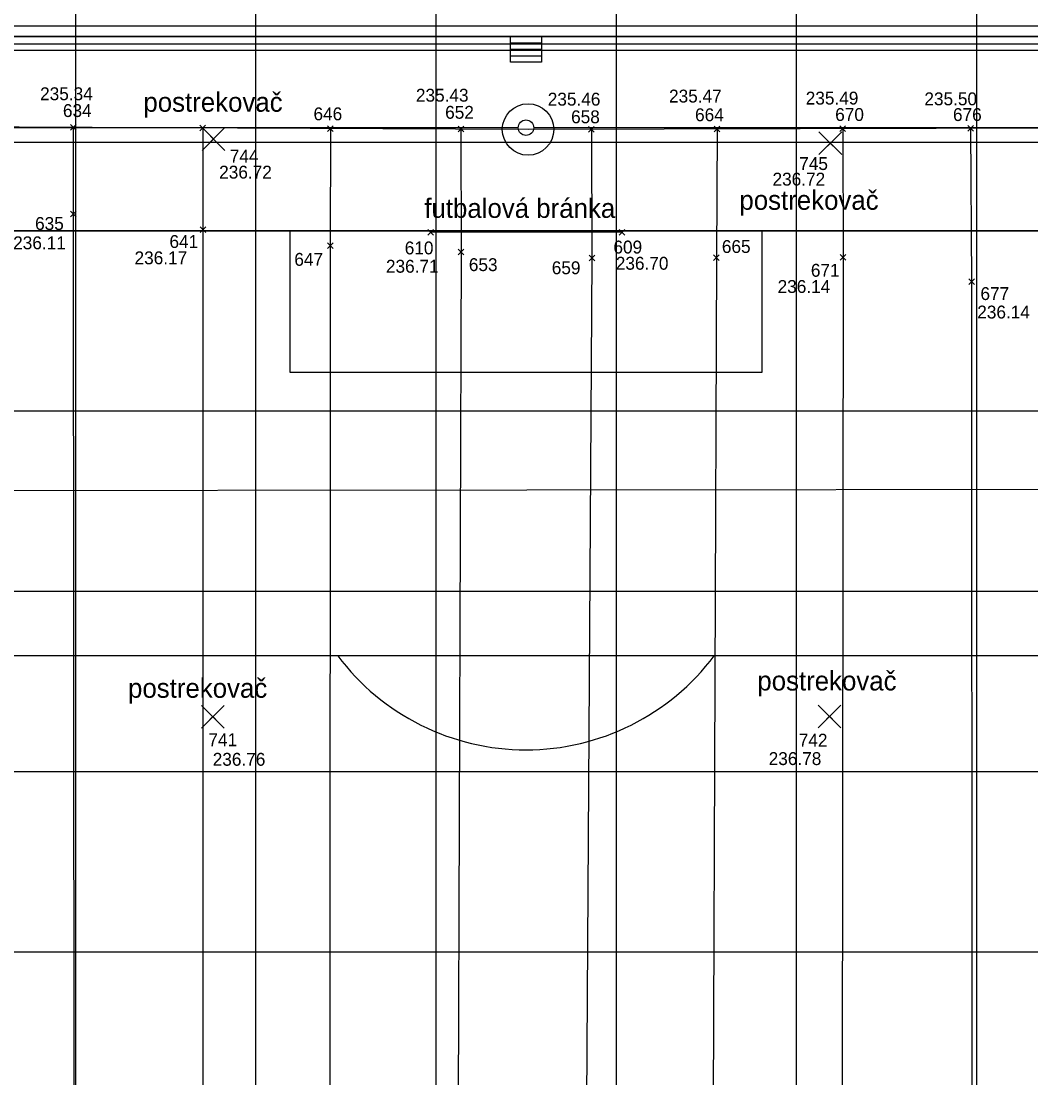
# Model space of a CAD drawing. Extents: x -264205 to -263659, y -1242401 to -1242060.
# Drawn here: x -263871.58 to -263832.36, y -1242144.77 to -1242103.74 of the extents above; entities that cross this region are included whole.
import ezdxf

# ---------------------------------------------------------------- set-up
doc = ezdxf.new("R2010")
doc.units = 0
for name, color, linetype in [('BOD_CISLO', 7, 'Continuous'), ('BOD_SYMBOL', 7, 'Continuous'), ('BOD_VYSKA', 7, 'Continuous'), ('KFA_SO_10-1_DRENAZNY_SYSTEM_IHRISKA', 7, 'Continuous'), ('KFA_SO_10-1_FUTBALOVE_BRANKY', 7, 'Continuous'), ('KFA_SO_10-1_POSTREKOVACE', 7, 'Continuous'), ('KFA_SO_10-1_TEPELNE_SENZORY_A_TRASA', 7, 'Continuous'), ('KFA_SO_40-2-II_DAZDOVA_KANALIZACIA', 7, 'Continuous'), ('OSI_STAVBY_KFA', 7, 'Continuous'), ('POPIS', 7, 'Continuous'), ('SITUACIA_DSP_2D', 7, 'Continuous')]:
    doc.layers.add(name, color=color, linetype=linetype)

msp = doc.modelspace()

# ---------------------------------------------------------------- linework, layer by layer
at = {"layer": 'BOD_SYMBOL'}
for p, q in [((-263869.661, -1242107.972), (-263869.44, -1242107.752)), ((-263869.44, -1242107.972), (-263869.661, -1242107.752)), ((-263864.632, -1242107.997), (-263864.41, -1242107.775)), ((-263864.41, -1242107.997), (-263864.632, -1242107.775)), ((-263859.674, -1242108.019), (-263859.453, -1242107.799)), ((-263859.453, -1242108.019), (-263859.674, -1242107.799)), ((-263854.607, -1242108.043), (-263854.386, -1242107.823)), ((-263854.386, -1242108.043), (-263854.607, -1242107.823)), ((-263849.538, -1242108.049), (-263849.317, -1242107.829)), ((-263849.317, -1242108.049), (-263849.538, -1242107.829)), ((-263844.656, -1242108.038), (-263844.435, -1242107.816)), ((-263844.435, -1242108.038), (-263844.656, -1242107.816)), ((-263839.773, -1242108.026), (-263839.552, -1242107.806)), ((-263839.552, -1242108.026), (-263839.773, -1242107.806)), ((-263834.812, -1242108.015), (-263834.59, -1242107.793)), ((-263834.59, -1242108.015), (-263834.812, -1242107.793)), ((-263864.217, -1242108.424), (-263863.996, -1242108.204)), ((-263863.996, -1242108.424), (-263864.217, -1242108.204)), ((-263840.258, -1242108.59), (-263840.036, -1242108.369)), ((-263840.036, -1242108.59), (-263840.258, -1242108.369)), ((-263869.666, -1242111.343), (-263869.445, -1242111.122)), ((-263869.445, -1242111.343), (-263869.666, -1242111.122)), ((-263864.628, -1242111.941), (-263864.406, -1242111.721)), ((-263864.406, -1242111.941), (-263864.628, -1242111.721)), ((-263855.777, -1242112.046), (-263855.556, -1242111.826)), ((-263855.556, -1242112.046), (-263855.777, -1242111.826)), ((-263848.354, -1242112.046), (-263848.133, -1242111.825)), ((-263848.133, -1242112.046), (-263848.354, -1242111.825)), ((-263859.679, -1242112.565), (-263859.458, -1242112.343)), ((-263859.458, -1242112.565), (-263859.679, -1242112.343)), ((-263854.603, -1242112.811), (-263854.382, -1242112.59)), ((-263854.382, -1242112.811), (-263854.603, -1242112.59)), ((-263849.516, -1242113.048), (-263849.295, -1242112.826)), ((-263849.295, -1242113.048), (-263849.516, -1242112.826)), ((-263844.685, -1242113.038), (-263844.464, -1242112.816)), ((-263844.464, -1242113.038), (-263844.685, -1242112.816)), ((-263839.764, -1242113.022), (-263839.542, -1242112.801)), ((-263839.542, -1242113.022), (-263839.764, -1242112.801)), ((-263834.773, -1242113.968), (-263834.552, -1242113.748)), ((-263834.552, -1242113.968), (-263834.773, -1242113.748)), ((-263864.242, -1242130.86), (-263864.02, -1242130.639)), ((-263864.02, -1242130.86), (-263864.242, -1242130.639)), ((-263840.29, -1242130.846), (-263840.068, -1242130.626)), ((-263840.068, -1242130.846), (-263840.29, -1242130.626))]:
    msp.add_line(p, q, dxfattribs=at)
at = {"layer": 'KFA_SO_10-1_DRENAZNY_SYSTEM_IHRISKA'}
for p, q in [((-263869.551, -1242107.862), (-263869.556, -1242111.232)), ((-263864.521, -1242107.886), (-263864.517, -1242111.831)), ((-263859.563, -1242107.909), (-263859.568, -1242112.454)), ((-263854.497, -1242107.933), (-263854.492, -1242112.7)), ((-263849.427, -1242107.939), (-263849.405, -1242112.937)), ((-263844.546, -1242107.927), (-263844.574, -1242112.927)), ((-263839.662, -1242107.916), (-263839.653, -1242112.911)), ((-263834.701, -1242107.904), (-263834.662, -1242113.858)), ((-263869.556, -1242111.232), (-263869.513, -1242164.723)), ((-263864.517, -1242111.831), (-263864.522, -1242164.519)), ((-263859.568, -1242112.454), (-263859.595, -1242163.194)), ((-263854.492, -1242112.7), (-263854.666, -1242163.281)), ((-263849.405, -1242112.937), (-263849.741, -1242163.884)), ((-263844.574, -1242112.927), (-263844.761, -1242164.295)), ((-263839.653, -1242112.911), (-263839.717, -1242164.47)), ((-263834.662, -1242113.858), (-263834.648, -1242164.01))]:
    msp.add_line(p, q, dxfattribs=at)
at = {"layer": 'KFA_SO_10-1_FUTBALOVE_BRANKY'}
msp.add_line((-263848.243, -1242111.935), (-263855.666, -1242111.936), dxfattribs=at)
at = {"layer": 'KFA_SO_10-1_POSTREKOVACE'}
for p, q in [((-263864.548, -1242108.756), (-263863.664, -1242107.872)), ((-263863.664, -1242108.756), (-263864.548, -1242107.872)), ((-263840.589, -1242108.921), (-263839.705, -1242108.037)), ((-263839.705, -1242108.921), (-263840.589, -1242108.037)), ((-263864.573, -1242131.191), (-263863.689, -1242130.307)), ((-263863.689, -1242131.191), (-263864.573, -1242130.307)), ((-263840.621, -1242131.178), (-263839.737, -1242130.294)), ((-263839.737, -1242131.178), (-263840.621, -1242130.294))]:
    msp.add_line(p, q, dxfattribs=at)
at = {"layer": 'KFA_SO_10-1_TEPELNE_SENZORY_A_TRASA'}
msp.add_lwpolyline([(-263827.921, -1242121.921), (-263875.963, -1242121.979), (-263885.626, -1242121.792), (-263887.003, -1242121.689), (-263887.052, -1242145.021), (-263887.18, -1242173.77), (-263887.177, -1242203.116), (-263886.892, -1242206.901)], dxfattribs=at)
at = {"layer": 'KFA_SO_40-2-II_DAZDOVA_KANALIZACIA'}
msp.add_lwpolyline([(-263814.907, -1242107.856), (-263851.887, -1242107.945), (-263888.606, -1242107.773), (-263888.523, -1242164.395), (-263888.701, -1242220.786)], dxfattribs=at)
msp.add_circle((-263851.887, -1242107.945), 1, dxfattribs=at)
at = {"layer": 'OSI_STAVBY_KFA'}
for p, q in [((-263869.468, -1242083.237), (-263869.468, -1242246.707)), ((-263862.468, -1242083.237), (-263862.468, -1242246.707)), ((-263855.468, -1242083.237), (-263855.468, -1242246.707)), ((-263848.468, -1242083.237), (-263848.468, -1242246.707)), ((-263841.468, -1242083.237), (-263841.468, -1242246.707)), ((-263834.468, -1242083.237), (-263834.468, -1242246.707)), ((-263792.653, -1242103.932), (-263911.523, -1242103.932)), ((-263792.653, -1242104.882), (-263911.523, -1242104.882)), ((-263792.653, -1242111.882), (-263911.523, -1242111.882)), ((-263792.653, -1242118.882), (-263917.453, -1242118.882)), ((-263792.653, -1242125.882), (-263909.343, -1242125.882)), ((-263792.653, -1242132.882), (-263917.293, -1242132.882)), ((-263792.653, -1242139.882), (-263909.343, -1242139.882))]:
    msp.add_line(p, q, dxfattribs=at)
at = {"layer": 'SITUACIA_DSP_2D'}
for p, q in [((-263887.916, -1242104.332), (-263816.02, -1242104.332)), ((-263816.02, -1242104.332), (-263887.916, -1242104.332)), ((-263852.567, -1242105.332), (-263852.567, -1242104.332)), ((-263851.369, -1242104.332), (-263851.369, -1242105.332)), ((-263816.144, -1242104.632), (-263887.792, -1242104.632)), ((-263852.567, -1242104.582), (-263851.369, -1242104.582)), ((-263852.567, -1242104.832), (-263851.369, -1242104.832)), ((-263852.567, -1242105.082), (-263851.369, -1242105.082)), ((-263851.369, -1242105.332), (-263852.567, -1242105.332)), ((-263852.268, -1242107.877), (-263888.373, -1242107.877)), ((-263815.563, -1242107.877), (-263851.668, -1242107.877)), ((-263887.968, -1242108.434), (-263815.968, -1242108.434)), ((-263885.968, -1242111.882), (-263817.968, -1242111.882)), ((-263872.128, -1242111.882), (-263831.808, -1242111.882)), ((-263861.128, -1242117.382), (-263861.128, -1242111.882)), ((-263861.128, -1242111.882), (-263842.808, -1242111.882)), ((-263842.808, -1242111.882), (-263842.808, -1242117.382)), ((-263842.808, -1242117.382), (-263861.128, -1242117.382)), ((-263831.808, -1242128.382), (-263872.128, -1242128.382))]:
    msp.add_line(p, q, dxfattribs=at)
msp.add_circle((-263851.968, -1242107.877), 0.3, dxfattribs=at)
msp.add_arc((-263851.968, -1242122.882), 9.15, 216.9482, 323.0518, dxfattribs=at)

# ---------------------------------------------------------------- texts
at = {"layer": 'BOD_CISLO'}
for s, p in [('634', (-263869.954, -1242107.462)), ('646', (-263860.221, -1242107.59)), ('652', (-263855.108, -1242107.53)), ('658', (-263850.216, -1242107.704)), ('664', (-263845.401, -1242107.625)), ('670', (-263839.958, -1242107.615)), ('676', (-263835.383, -1242107.617)), ('744', (-263863.473, -1242109.23)), ('745', (-263841.356, -1242109.52)), ('635', (-263871.036, -1242111.847)), ('641', (-263865.816, -1242112.546)), ('610', (-263856.677, -1242112.795)), ('609', (-263848.572, -1242112.761)), ('665', (-263844.36, -1242112.741)), ('647', (-263860.966, -1242113.239)), ('653', (-263854.188, -1242113.444)), ('659', (-263850.967, -1242113.565)), ('671', (-263840.903, -1242113.663)), ('677', (-263834.317, -1242114.568)), ('741', (-263864.304, -1242131.891)), ('742', (-263841.373, -1242131.907))]:
    msp.add_text(s, height=0.5, dxfattribs=at).set_placement(p)
at = {"layer": 'BOD_VYSKA'}
for s, p in [('235.34', (-263870.84, -1242106.809)), ('235.43', (-263856.244, -1242106.866)), ('235.47', (-263846.412, -1242106.899)), ('235.46', (-263851.123, -1242107.018)), ('235.49', (-263841.103, -1242106.978)), ('235.50', (-263836.494, -1242107.007)), ('236.72', (-263863.885, -1242109.852)), ('236.72', (-263842.392, -1242110.124)), ('236.11', (-263871.887, -1242112.597)), ('236.17', (-263867.172, -1242113.18)), ('236.70', (-263848.48, -1242113.391)), ('236.71', (-263857.408, -1242113.507)), ('236.14', (-263842.195, -1242114.293)), ('236.14', (-263834.441, -1242115.284)), ('236.76', (-263864.136, -1242132.649)), ('236.78', (-263842.542, -1242132.622))]:
    msp.add_text(s, height=0.5, dxfattribs=at).set_placement(p)
at = {"layer": 'POPIS'}
for s, p in [('postrekovač', (-263866.828, -1242107.258)), ('postrekovač', (-263843.679, -1242111.064)), ('futbalová bránka', (-263855.918, -1242111.378)), ('postrekovač', (-263842.983, -1242129.727)), ('postrekovač', (-263867.425, -1242130.01))]:
    msp.add_text(s, height=0.75, dxfattribs=at).set_placement(p)

doc.saveas('drawing.dxf')
